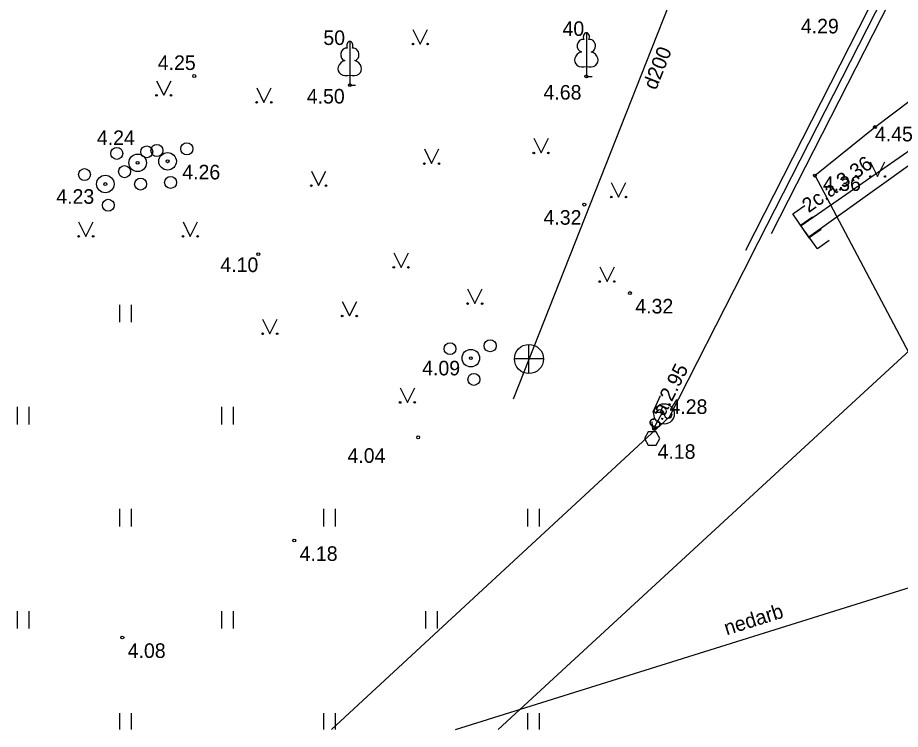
# Model space of a CAD drawing. Extents: x 484635 to 484808, y 278866 to 278977.
# Drawn here: x 484725.5 to 484755.78, y 278866.04 to 278890.45 of the extents above; entities that cross this region are included whole.
import ezdxf

# ---------------------------------------------------------------- set-up
doc = ezdxf.new("R2010")
doc.units = 0
for name, color, linetype in [('CKOM_ELEM_####_####_#', 7, 'Continuous'), ('GAZE_ELEM_####_####_#', 7, 'Continuous'), ('GAZE_ELEM_####_TKST_#', 7, 'Continuous'), ('GAZE_VADP_KONT_####_#', 7, 'Continuous'), ('GAZE_VADP_VSP1_####_#', 7, 'Continuous'), ('GAZE_VADP_VSP1_TKST_#', 7, 'Continuous'), ('GAZE_VADP_VSP2_####_#', 7, 'Continuous'), ('NORB_ZOGS_ZSTP_####_#', 7, 'Continuous'), ('RELJ_AATZ_####_TKST_#', 7, 'Continuous'), ('RELJ_ELEM_####_####_#', 7, 'Continuous'), ('SILT_ELEM_####_####_#', 7, 'Continuous'), ('SILT_VADP_UDEN_####_I', 7, 'Continuous'), ('SILT_VADP_UDEN_TKST_I', 7, 'Continuous'), ('SKAN_ELEM_####_####_#', 7, 'Continuous'), ('SKAN_VADP_NEDR_####_#', 7, 'Continuous'), ('SKAN_VADP_NEDR_TKST_#', 7, 'Continuous'), ('SKAN_VADP_SPDK_TKST_#', 7, 'Continuous'), ('TERT_DIAM_####_TKST_#', 7, 'Continuous'), ('TERT_ELEM_####_####_#', 7, 'Continuous'), ('UDTK_VADP_NEDR_####_#', 7, 'Continuous')]:
    doc.layers.add(name, color=color, linetype=linetype)

msp = doc.modelspace()

# ---------------------------------------------------------------- linework, layer by layer
at = {"layer": 'CKOM_ELEM_####_####_#'}
msp.add_line((484747.289, 278876.319), (484747.53, 278876.458), dxfattribs=at)
msp.add_lwpolyline([(484747.538, 278877.481), (484747.289, 278876.918), (484747.625, 278876.918), (484747.289, 278876.319), (484747.267, 278876.589)], dxfattribs=at)
msp.add_lwpolyline([(484747.133, 278875.789), (484747.399, 278875.789), (484747.532, 278876.019), (484747.399, 278876.25), (484747.133, 278876.25), (484747, 278876.019)], close=True, dxfattribs=at)
at = {"layer": 'GAZE_ELEM_####_####_#'}
msp.add_circle((484747.674, 278876.859), 0.35, dxfattribs=at)
for centre, start, end in [((484747.534, 278876.859), 0, 180), ((484747.814, 278876.859), 180, 0)]:
    msp.add_arc(centre, 0.14, start, end, dxfattribs=at)
at = {"layer": 'GAZE_VADP_KONT_####_#'}
for points in [[(484750.477, 278882.479), (484757.277, 278895.824), (484768.894, 278918.779), (484766.279, 278933.523), (484765.094, 278950.654), (484769.76, 278961.533)], [(484751.36, 278883.044), (484757.749, 278895.584), (484769.446, 278918.697), (484766.805, 278933.587), (484765.632, 278950.562), (484770.25, 278961.331)]]:
    msp.add_lwpolyline(points, dxfattribs=at)
at = {"layer": 'GAZE_VADP_VSP1_####_#'}
msp.add_lwpolyline([(484747.86, 278876.76), (484736.267, 278866.043)], dxfattribs=at)
at = {"layer": 'GAZE_VADP_VSP2_####_#'}
for points in [[(484750.918, 278882.762), (484757.513, 278895.704), (484769.17, 278918.738), (484766.542, 278933.555), (484765.363, 278950.608), (484770.005, 278961.432)], [(484750.409, 278881.762), (484750.918, 278882.762)], [(484747.86, 278876.76), (484750.409, 278881.762)]]:
    msp.add_lwpolyline(points, dxfattribs=at)
at = {"layer": 'NORB_ZOGS_ZSTP_####_#'}
for p, q in [((484752.846, 278885.031), (484754.908, 278886.695)), ((484752.851, 278885.041), (484758.705, 278873.968))]:
    msp.add_line(p, q, dxfattribs=at)
msp.add_lwpolyline([(484754.908, 278886.695), (484770.847, 278898.725)], dxfattribs=at)
at = {"layer": 'RELJ_ELEM_####_####_#'}
for centre in [(484731.558, 278888.446), (484745.009, 278888.431), (484736.894, 278888.133), (484754.908, 278886.695), (484730.643, 278885.522), (484729.615, 278885.468), (484752.846, 278885.031), (484728.507, 278884.742), (484744.939, 278884.036), (484733.755, 278882.337), (484746.503, 278881.003), (484741.047, 278878.771), (484739.24, 278876.057), (484734.988, 278872.519), (484729.09, 278869.192)]:
    msp.add_circle(centre, 0.05, dxfattribs=at)
at = {"layer": 'SILT_ELEM_####_####_#'}
for points in [[(484753.069, 278883.182), (484752.658, 278882.897), (484752.089, 278883.719), (484752.5, 278884.004)], [(484753.341, 278882.807), (484752.934, 278882.517), (484752.353, 278883.331), (484752.761, 278883.621)]]:
    msp.add_lwpolyline(points, dxfattribs=at)
at = {"layer": 'SILT_VADP_UDEN_####_I'}
for points in [[(484758.542, 278887.583), (484752.374, 278883.308)], [(484756.145, 278885.419), (484752.644, 278882.924)]]:
    msp.add_lwpolyline(points, dxfattribs=at)
at = {"layer": 'SKAN_ELEM_####_####_#'}
for p, q in [((484743.04, 278878.243), (484743.04, 278879.243)), ((484743.54, 278878.743), (484742.54, 278878.743))]:
    msp.add_line(p, q, dxfattribs=at)
msp.add_circle((484743.04, 278878.743), 0.5, dxfattribs=at)
at = {"layer": 'SKAN_VADP_NEDR_####_#'}
for points in [[(484742.504, 278877.375), (484747.25, 278889.386), (484751.85, 278901.026)], [(484740.521, 278866.043), (484756.132, 278870.921)]]:
    msp.add_lwpolyline(points, dxfattribs=at)
at = {"layer": 'TERT_ELEM_####_####_#'}
for p, q in [((484739.062, 278890.041), (484739.312, 278889.541)), ((484739.312, 278889.541), (484739.562, 278890.041)), ((484745.009, 278888.778), (484745.009, 278888.431)), ((484730.263, 278888.285), (484730.513, 278887.785)), ((484730.513, 278887.785), (484730.763, 278888.285)), ((484736.894, 278888.48), (484736.894, 278888.133)), ((484745.009, 278888.431), (484745.209, 278888.431)), ((484733.7, 278888.041), (484733.95, 278887.541)), ((484733.95, 278887.541), (484734.2, 278888.041)), ((484736.894, 278888.133), (484737.094, 278888.133)), ((484743.205, 278886.31), (484743.455, 278885.81)), ((484743.455, 278885.81), (484743.705, 278886.31)), ((484739.451, 278885.944), (484739.701, 278885.444)), ((484739.701, 278885.444), (484739.951, 278885.944)), ((484754.75, 278885.5), (484755, 278885)), ((484755, 278885), (484755.25, 278885.5)), ((484735.576, 278885.188), (484735.826, 278884.688)), ((484735.826, 278884.688), (484736.076, 278885.188)), ((484745.865, 278884.796), (484746.115, 278884.296)), ((484746.115, 278884.296), (484746.365, 278884.796)), ((484727.59, 278883.448), (484727.84, 278882.948)), ((484727.84, 278882.948), (484728.09, 278883.448)), ((484731.173, 278883.448), (484731.423, 278882.948)), ((484731.423, 278882.948), (484731.673, 278883.448)), ((484738.403, 278882.383), (484738.653, 278881.883)), ((484738.653, 278881.883), (484738.903, 278882.383)), ((484745.469, 278881.9), (484745.719, 278881.4)), ((484745.719, 278881.4), (484745.969, 278881.9)), ((484740.935, 278881.144), (484741.185, 278880.644)), ((484741.185, 278880.644), (484741.435, 278881.144)), ((484736.632, 278880.717), (484736.882, 278880.217)), ((484736.882, 278880.217), (484737.132, 278880.717)), ((484729, 278880), (484729, 278880.6)), ((484729.4, 278880), (484729.4, 278880.6)), ((484733.902, 278880.107), (484734.152, 278879.607)), ((484734.152, 278879.607), (484734.402, 278880.107)), ((484738.62, 278877.753), (484738.87, 278877.253)), ((484738.87, 278877.253), (484739.12, 278877.753)), ((484725.5, 278876.5), (484725.5, 278877.1)), ((484725.9, 278876.5), (484725.9, 278877.1)), ((484732.5, 278876.5), (484732.5, 278877.1)), ((484732.9, 278876.5), (484732.9, 278877.1)), ((484729, 278873), (484729, 278873.6)), ((484729.4, 278873), (484729.4, 278873.6)), ((484736, 278873), (484736, 278873.6)), ((484736.4, 278873), (484736.4, 278873.6)), ((484743, 278873), (484743, 278873.6)), ((484743.4, 278873), (484743.4, 278873.6)), ((484725.5, 278869.5), (484725.5, 278870.1)), ((484725.9, 278869.5), (484725.9, 278870.1)), ((484732.5, 278869.5), (484732.5, 278870.1)), ((484732.9, 278869.5), (484732.9, 278870.1)), ((484739.5, 278869.5), (484739.5, 278870.1)), ((484739.9, 278869.5), (484739.9, 278870.1)), ((484729, 278866.043), (484729, 278866.6)), ((484729.4, 278866.043), (484729.4, 278866.6)), ((484736, 278866.043), (484736, 278866.6)), ((484736.4, 278866.043), (484736.4, 278866.6)), ((484743, 278866.043), (484743, 278866.6)), ((484743.4, 278866.043), (484743.4, 278866.6))]:
    msp.add_line(p, q, dxfattribs=at)
for points in [[(484745.009, 278889.931), (484745.009, 278888.778)], [(484736.894, 278889.633), (484736.894, 278888.48)], [(484745.099, 278889.699), (484745.098, 278889.7)], [(484736.984, 278889.4), (484736.983, 278889.401)]]:
    msp.add_lwpolyline(points, dxfattribs=at)
for centre, radius in [((484739.061, 278889.541), 0.028), ((484739.561, 278889.541), 0.0263), ((484730.263, 278887.785), 0.028), ((484730.763, 278887.785), 0.0263), ((484733.699, 278887.541), 0.028), ((484734.199, 278887.541), 0.0263), ((484731.304, 278885.947), 0.207), ((484728.901, 278885.792), 0.204), ((484729.929, 278885.846), 0.204), ((484730.277, 278885.893), 0.207), ((484730.643, 278885.522), 0.301), ((484743.205, 278885.809), 0.028), ((484743.705, 278885.809), 0.0263), ((484729.615, 278885.468), 0.301), ((484727.793, 278885.066), 0.204), ((484729.168, 278885.167), 0.207), ((484739.451, 278885.443), 0.028), ((484739.951, 278885.443), 0.0263), ((484728.507, 278884.742), 0.301), ((484729.719, 278884.74), 0.205), ((484730.746, 278884.795), 0.205), ((484754.75, 278885), 0.028), ((484755.25, 278885), 0.0263), ((484735.576, 278884.687), 0.028), ((484736.076, 278884.687), 0.0263), ((484745.865, 278884.295), 0.028), ((484746.365, 278884.295), 0.0263), ((484728.61, 278884.015), 0.205), ((484727.59, 278882.948), 0.028), ((484728.09, 278882.948), 0.0263), ((484731.172, 278882.948), 0.028), ((484731.672, 278882.948), 0.0263), ((484738.403, 278881.883), 0.028), ((484738.903, 278881.883), 0.0263), ((484745.468, 278881.399), 0.028), ((484745.968, 278881.399), 0.0263), ((484740.935, 278880.643), 0.028), ((484741.435, 278880.643), 0.0263), ((484736.632, 278880.216), 0.028), ((484737.132, 278880.216), 0.0263), ((484733.902, 278879.607), 0.028), ((484734.402, 278879.607), 0.0263), ((484740.333, 278879.095), 0.204), ((484741.708, 278879.196), 0.207), ((484741.047, 278878.771), 0.301), ((484741.15, 278878.043), 0.205), ((484738.62, 278877.253), 0.028), ((484739.12, 278877.253), 0.0263)]:
    msp.add_circle(centre, radius, dxfattribs=at)
for centre, major_axis, ratio, start_param, end_param in [((484745.009, 278889.781), (0, -0.15), 0.707107, 3.14537, 5.287485), ((484745.009, 278889.781), (0, -0.15), 0.707107, 0.995701, 3.137816), ((484736.894, 278889.483), (0, -0.15), 0.707107, 3.14537, 5.287485), ((484736.894, 278889.483), (0, -0.15), 0.707107, 0.995701, 3.137816), ((484744.881, 278889.487), (-0.039, -0.212), 0.861323, 3.141593, 6.283185), ((484745.137, 278889.487), (0.039, -0.212), 0.861323, 0, 3.141593), ((484736.766, 278889.188), (-0.039, -0.212), 0.861323, 3.141593, 6.283185), ((484737.022, 278889.188), (0.039, -0.212), 0.861323, 0, 3.141593), ((484744.919, 278889.024), (0.307, 0.095), 0.814445, 1.570796, 4.752015), ((484745.099, 278889.024), (-0.307, 0.095), 0.814445, 1.531171, 4.712389), ((484736.805, 278888.725), (0.307, 0.095), 0.814445, 1.570796, 4.752015), ((484736.984, 278888.725), (-0.307, 0.095), 0.814445, 1.531171, 4.712389)]:
    msp.add_ellipse(centre, major_axis=major_axis, ratio=ratio, start_param=start_param, end_param=end_param, dxfattribs=at)
at = {"layer": 'UDTK_VADP_NEDR_####_#'}
for points in [[(484753.238, 278876.403), (484757.275, 278880.118), (484799.521, 278904.942)], [(484741.979, 278866.043), (484753.238, 278876.403)]]:
    msp.add_lwpolyline(points, dxfattribs=at)

# ---------------------------------------------------------------- texts
at = {"layer": 'GAZE_ELEM_####_TKST_#'}
msp.add_text(' 4.28', height=0.5, dxfattribs=at).set_placement((484747.674, 278876.859))
at = {"layer": 'GAZE_VADP_VSP1_TKST_#'}
msp.add_text('c.a.2.95', height=0.5, rotation=63.3134, dxfattribs=at).set_placement((484747.455, 278876.293))
at = {"layer": 'RELJ_AATZ_####_TKST_#'}
for s, p in [('4.29', (484752.367, 278889.907)), ('4.25', (484730.307, 278888.653)), ('4.50', (484735.418, 278887.503)), ('4.68', (484743.54, 278887.637)), ('4.24', (484728.218, 278886.08)), ('4.45', (484754.908, 278886.205)), ('4.26', (484731.147, 278884.901)), ('4.36', (484753.126, 278884.507)), ('4.23', (484726.825, 278884.065)), ('4.32', (484743.54, 278883.347)), ('4.10', (484732.454, 278881.723)), (' 4.32', (484746.503, 278880.303)), ('4.09', (484739.377, 278878.181)), (' 4.04', (484736.629, 278875.181)), (' 4.18', (484747.266, 278875.319)), (' 4.18', (484734.988, 278871.819)), (' 4.08', (484729.09, 278868.492))]:
    msp.add_text(s, height=0.5, dxfattribs=at).set_placement(p)
at = {"layer": 'SILT_VADP_UDEN_TKST_I'}
msp.add_text('2c.a.3.36', height=0.5, rotation=35.477, dxfattribs=at).set_placement((484752.632, 278883.737))
at = {"layer": 'SKAN_VADP_NEDR_TKST_#'}
msp.add_text('d200', height=0.5, rotation=68.4364, dxfattribs=at).set_placement((484747.401, 278887.94))
at = {"layer": 'SKAN_VADP_SPDK_TKST_#'}
msp.add_text('nedarb', height=0.5, rotation=17.354, dxfattribs=at).set_placement((484749.822, 278869.264))
at = {"layer": 'TERT_DIAM_####_TKST_#'}
for s, p in [('40', (484744.191, 278889.821)), ('50', (484735.987, 278889.51))]:
    msp.add_text(s, height=0.5, dxfattribs=at).set_placement(p)

doc.saveas('drawing.dxf')
